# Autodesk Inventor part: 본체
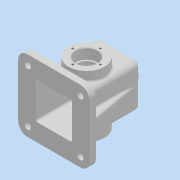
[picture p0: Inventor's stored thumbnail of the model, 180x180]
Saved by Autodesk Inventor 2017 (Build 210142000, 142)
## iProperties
Part Number: 본체
Material: 일반
Document SubType Name: Modeling
Designer: MRC
Density: 1 g/cm^3
Appearance: 기본값
Author: MRC
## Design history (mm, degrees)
sketch "스케치1"
  geometry: L1 (34, -52.5)-(-34, -52.5); L2 (-34, -52.5)-(-34, 52.5); L3 (-34, 52.5)-(34, 52.5); L4 (34, 52.5)-(34, -52.5); L5 (34, -52.5)-(-34, 52.5); L6 (-34, -52.5)-(34, 52.5); 1 further point
  constraints: 12 end point, 2 midpoint, 2 parallel, 1 horizontal, 1 perpendicular
  dimensions: "d0" = 68 distance of L2.end L3.end; "d1" = 105 distance of L1.end L2.end
extrude "돌출1" new body sketch "스케치1" stored distance "d2" = 68; taper "d3" = 0 deg
sketch "스케치2"
  geometry: L1 (5, -5)-(63, -5); L2 (63, -5)-(63, -63); L3 (63, -63)-(5, -63); L4 (5, -63)-(5, -5); L5 (5, -5)-(63, -63); L6 (63, -5)-(5, -63); 1 further point
  constraints: 12 end point, 2 midpoint, 2 parallel, 1 horizontal, 1 perpendicular
  dimensions: "d4" = 58 distance of L2.end L3.end; "d5" = 58 distance of L1.end L2.end
extrude "돌출2" cut sketch "스케치2" distance "d6" = 100; taper "d7" = 0 deg
sketch "스케치3"
  geometry: L1 (-34, -52.5)-(34, -52.5) reference; C1 r 28.5 at (0, -0.5); 1 further point
  constraints: 1 centre point, 1 vertical alignment
  dimensions: "d8" = 52 distance from line of C1.centre L1; "d9" = 57 diameter of C1
extrude "돌출3" join sketch "스케치3" distance "d10" = 15; taper "d11" = 0 deg
hole "구멍1" diameter "d14" = 30; stored, may be unused: countersink angle "d18" = 90 deg, drill point angle "d20" = 118 deg; dims "d12" = 10, "d13" = 10, "d15" = 6, "d16" = 35, "d17" = 17, "d19" = 8
sketch "스케치4"
  geometry: C1 r 17.5 at (0, 0) reference; 2 further points
  constraints: 1 vertical alignment
  dimensions: "d21" = 22 distance of point (0, 22) C1.centre
hole "구멍2" sketch "스케치4" at (0, 22) diameter "d22" = 3.242; stored, may be unused: countersink angle "d26" = 90 deg, drill point angle "d28" = 118 deg; dims "d23" = 8, "d24" = 35, "d25" = 17, "d27" = 10
fillet "모깎기1" dims "d29" = 8
node "작업 평면1"
sketch "스케치5"
  geometry: C1 r 20 at (-26, 34); 1 further point
  constraints: 1 centre point, 1 coincident
  dimensions: "d34" = 40 diameter of C1
extrude "돌출4" join sketch "스케치5" stored distance "d35" = 15; taper "d36" = 8 deg
hole "구멍3" diameter "d39" = 22.835; stored, may be unused: countersink angle "d43" = 90 deg, drill point angle "d45" = 118 deg; dims "d37" = 10, "d38" = 10, "d40" = 50, "d41" = 35, "d42" = 17, "d44" = 59.3
node "작업 평면2"
sketch "스케치6"
  geometry: L1 (0, 0)-(0, 52) reference; L2 (-60, 60)-(-8, 60) reference; L3 (-68, 52)-(-68, 0) reference; L4 (-8, -8)-(-60, -8) reference; L5 (23, 83)-(-91, 83); L6 (-91, 83)-(-91, -31); L7 (-91, -31)-(23, -31); L8 (23, -31)-(23, 83); L9 (23, 83)-(-91, -31); L10 (-91, 83)-(23, -31); A1 r 8 centre (-8, 52) between (0, 52) and (-8, 60) reference; A2 r 8 centre (-60, 52) between (-60, 60) and (-68, 52) reference; A3 r 8 centre (-60, 0) between (-68, 0) and (-60, -8) reference; A4 r 8 centre (-8, 0) between (-8, -8) and (0, 0) reference; 1 further point
  constraints: 12 end point, 2 midpoint, 2 parallel, 1 horizontal, 1 perpendicular
  dimensions: "d46" = 114 distance of L7.end L6.end; "d47" = 114 distance of L6.end L5.end
extrude "돌출5" join sketch "스케치6" distance "d48" = 10; taper "d49" = 0 deg
sketch "스케치7"
  geometry: 2 further points
  dimensions: "d50" = 42 horizontal distance of point (-76, -68) point (-34, -26); "d51" = 42 horizontal distance of point (-76, -68) point (-34, -26)
fillet "모깎기2" dims "d52" = 15
hole "구멍4" sketch "스케치7" diameter "d53" = 10; stored, may be unused: countersink angle "d57" = 90 deg, drill point angle "d59" = 0 deg; dims "d54" = 50, "d55" = 18, "d56" = 2, "d58" = 59.3
chamfer "모따기1" distance "d60" = 1; stored, may be unused: second distance "d61" = 2, angle "d62" = 45 deg
sketch "스케치8"
  geometry: L1 (-43.772, -12.848)-(-49, -42.5); L2 (-57, -42.5)-(-57, -52.5) reference; L3 (-51, -42.5)-(-33, -42.5) reference; 1 further point
  constraints: 2 end point, 1 point on line
  dimensions: "d63" = 10 deg angle of L2 L1; "d64" = 8 distance from line of L2 L1.end
feature "리브1" sketch "스케치8" dims "d65" = 1, "d66" = 10, "d67" = 0, "d68" = 0, "d69" = 1, "d70" = 1
fillet "모깎기3" dims "d71" = 3
fillet "모깎기4" dims "d72" = 0.3
fillet "모깎기5" dims "d73" = 3
sketch "스케치9"
  geometry: L1 (-34, 44.5)-(-34, -39.5) reference; L2 (-20, 62.5)-(20, 62.5) reference; 2 further points
  constraints: 1 other
  dimensions: "d74" = 34 distance from line of L1 point (0, 37.5); "d75" = 25 distance from line of L2 point (0, 37.5)
feature "엠보싱1" sketch "스케치9" dims "d0" = 68, "d1" = 105, "d8" = 52, "d9" = 57, "d76" = 0.5, "d77" = 0
node "솔리드1"
pattern_circular "원형 패턴1" dims angle "d31" = 360 deg
mirror "미러1"
mirror "미러2"
mirror "미러3"
mirror "미러4"
other parameters: "d33" = -115
